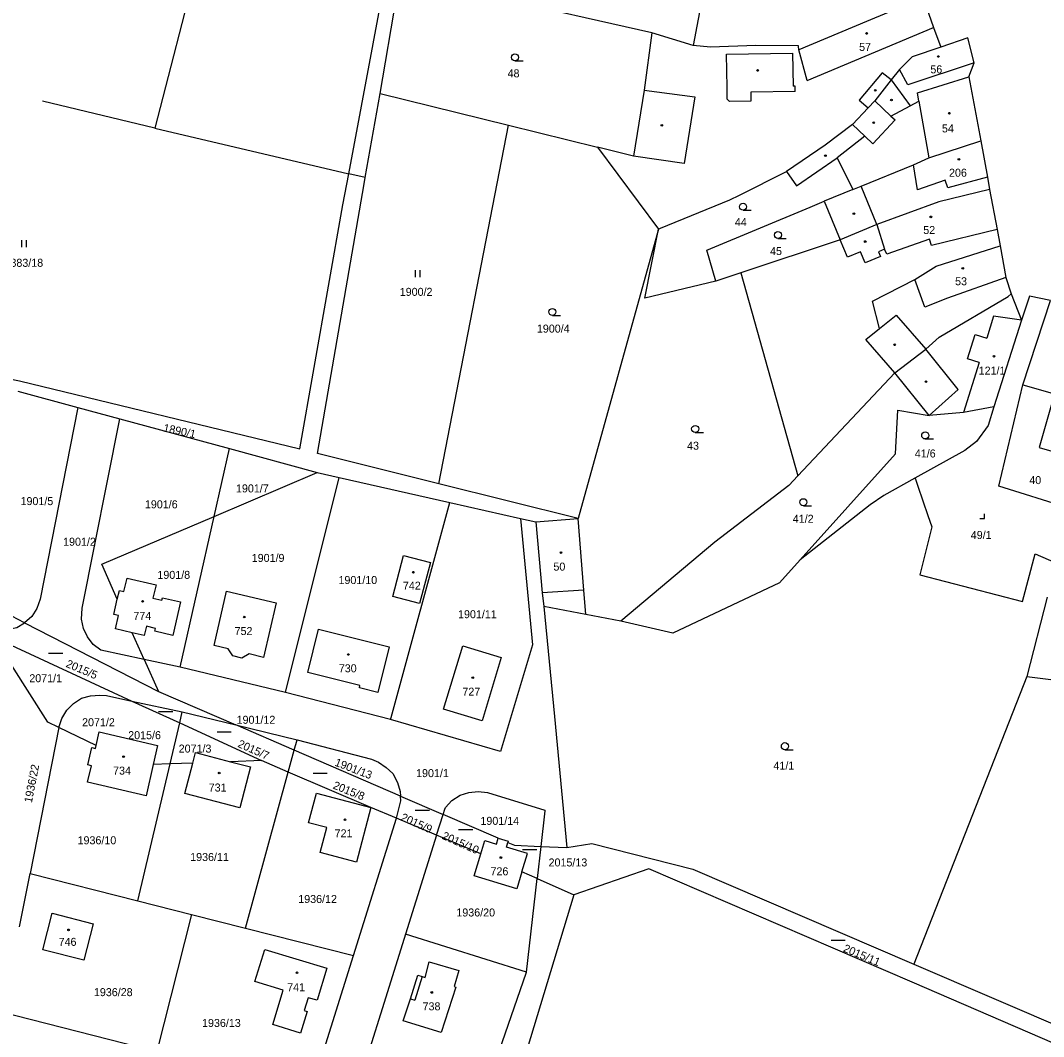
# Model space of a CAD drawing. Extents: x -793666 to -785424, y -1118958 to -1108761.
# Drawn here: x -788490.9 to -788273.7, y -1116664.5 to -1116448.6 of the extents above; entities that cross this region are included whole.
import ezdxf

# ---------------------------------------------------------------- set-up
doc = ezdxf.new("R2010")
doc.units = 0
for name, color, linetype in [('Hranice parcel', 7, 'Continuous'), ('Parcelní čísla', 7, 'Continuous'), ('Vnitřní kresba', 7, 'Continuous'), ('Značky budov', 7, 'Continuous'), ('Značky kultur', 7, 'Continuous')]:
    doc.layers.add(name, color=color, linetype=linetype)

msp = doc.modelspace()

# ---------------------------------------------------------------- linework, layer by layer
at = {"layer": 'Hranice parcel'}
for p, q in [((-788414.54, -1116464.14), (-788410.35, -1116439.11)), ((-788356.85, -1116451.26), (-788410.35, -1116439.11)), ((-788348.08, -1116453.93), (-788356.85, -1116451.26)), ((-788289.56, -1116460.58), (-788286.99, -1116474.21)), ((-788417.71, -1116481.98), (-788414.54, -1116464.14)), ((-788414.54, -1116464.14), (-788387.31, -1116470.88)), ((-788462.39, -1116471.52), (-788486.23, -1116465.77)), ((-788402.13, -1116547.05), (-788387.31, -1116470.88)), ((-788387.31, -1116470.88), (-788368.39, -1116475.54)), ((-788462.39, -1116471.52), (-788421.23, -1116481.16)), ((-788368.39, -1116475.54), (-788355.49, -1116492.94)), ((-788417.71, -1116481.98), (-788421.23, -1116481.16)), ((-788314.17, -1116484.54), (-788320.25, -1116487.03)), ((-788320.25, -1116487.03), (-788316.88, -1116495.2)), ((-788355.49, -1116492.94), (-788372.54, -1116554.44)), ((-788316.88, -1116495.2), (-788338.01, -1116502.23)), ((-788338.01, -1116502.23), (-788343.25, -1116503.97)), ((-788338.01, -1116502.23), (-788325.84, -1116545.35)), ((-788280.56, -1116506.71), (-788278.35, -1116512.25)), ((-788278.12, -1116526), (-788272.23, -1116508.1)), ((-788278.35, -1116512.25), (-788284.27, -1116530.68)), ((-788305.27, -1116523.5), (-788325.84, -1116545.35)), ((-788297.98, -1116532.55), (-788305.27, -1116523.5)), ((-788491.48, -1116527.33), (-788478.73, -1116530.8)), ((-788478.73, -1116530.8), (-788469.84, -1116533.23)), ((-788469.84, -1116533.23), (-788446.58, -1116539.57)), ((-788449.82, -1116553.98), (-788446.58, -1116539.57)), ((-788446.58, -1116539.57), (-788427.9, -1116544.66)), ((-788290.41, -1116539.96), (-788301, -1116545.84)), ((-788449.82, -1116553.98), (-788427.9, -1116544.66)), ((-788427.9, -1116544.66), (-788423.28, -1116545.71)), ((-788434.66, -1116591.36), (-788423.28, -1116545.71)), ((-788423.28, -1116545.71), (-788399.74, -1116551.03)), ((-788301, -1116545.84), (-788307.59, -1116549.5)), ((-788372.54, -1116554.44), (-788402.13, -1116547.05)), ((-788399.74, -1116551.03), (-788384.76, -1116554.42)), ((-788307.59, -1116549.5), (-788310.51, -1116551.48)), ((-788310.51, -1116551.48), (-788325.4, -1116563.23)), ((-788457.04, -1116586.01), (-788449.82, -1116553.98)), ((-788384.76, -1116554.42), (-788381.52, -1116555.15)), ((-788381.52, -1116555.15), (-788372.54, -1116554.44)), ((-788470.37, -1116571.57), (-788469.94, -1116569.69)), ((-788471.11, -1116574.8), (-788470.37, -1116571.57)), ((-788272.94, -1116571.1), (-788277.22, -1116587.97)), ((-788490.08, -1116576.56), (-788492.74, -1116575.19)), ((-788370.92, -1116574.81), (-788379.78, -1116573.09)), ((-788363.45, -1116576.26), (-788370.92, -1116574.81)), ((-788490.08, -1116576.56), (-788461.64, -1116591.17)), ((-788467.2, -1116578.68), (-788470.78, -1116577.86)), ((-788464.67, -1116584.38), (-788467.2, -1116578.68)), ((-788464.65, -1116579.27), (-788467.2, -1116578.68)), ((-788496.63, -1116579.65), (-788467.26, -1116593.19)), ((-788457.04, -1116586.01), (-788464.67, -1116584.38)), ((-788464.67, -1116584.38), (-788461.64, -1116591.17)), ((-788434.66, -1116591.36), (-788457.04, -1116586.01)), ((-788277.22, -1116587.97), (-788301.21, -1116649.08)), ((-788277.22, -1116587.97), (-788263.13, -1116589.78)), ((-788461.64, -1116591.17), (-788445.21, -1116598.27)), ((-788412.36, -1116597.13), (-788434.66, -1116591.36)), ((-788467.26, -1116593.19), (-788456.58, -1116595.52)), ((-788467.26, -1116593.19), (-788457.13, -1116597.86)), ((-788457.13, -1116597.86), (-788456.58, -1116595.52)), ((-788456.58, -1116595.52), (-788445.21, -1116598.27)), ((-788482.78, -1116598.82), (-788488.9, -1116629.83)), ((-788474.89, -1116602.67), (-788482.78, -1116598.82)), ((-788459.18, -1116606.54), (-788457.13, -1116597.86)), ((-788457.13, -1116597.86), (-788439.79, -1116605.86)), ((-788445.21, -1116598.27), (-788432.2, -1116601.41)), ((-788432.81, -1116603.63), (-788445.21, -1116598.27)), ((-788474.89, -1116602.67), (-788474.22, -1116599.75)), ((-788474.22, -1116599.75), (-788461.82, -1116602.62)), ((-788475.02, -1116603.25), (-788474.89, -1116602.67)), ((-788461.82, -1116602.62), (-788462.75, -1116606.67)), ((-788432.81, -1116603.63), (-788432.2, -1116601.41)), ((-788434.08, -1116608.29), (-788432.81, -1116603.63)), ((-788410.24, -1116613.38), (-788432.81, -1116603.63)), ((-788466.02, -1116635.65), (-788459.18, -1116606.54)), ((-788462.75, -1116606.67), (-788464.27, -1116613.33)), ((-788459.18, -1116606.54), (-788462.75, -1116606.67)), ((-788454.34, -1116606.37), (-788459.18, -1116606.54)), ((-788439.79, -1116605.86), (-788446.34, -1116606.09)), ((-788434.08, -1116608.29), (-788439.79, -1116605.86)), ((-788443.12, -1116641.46), (-788434.08, -1116608.29)), ((-788410.24, -1116613.38), (-788401.19, -1116617.29)), ((-788379.57, -1116616.52), (-788380.44, -1116624.08)), ((-788420.23, -1116647.28), (-788411.08, -1116618.07)), ((-788402.57, -1116621.69), (-788411.08, -1116618.07)), ((-788402.57, -1116621.69), (-788401.19, -1116617.29)), ((-788389.49, -1116622.34), (-788401.19, -1116617.29)), ((-788402.57, -1116621.69), (-788409.17, -1116642.74)), ((-788393.2, -1116625.68), (-788402.57, -1116621.69)), ((-788380.44, -1116624.08), (-788381.23, -1116630.92)), ((-788380.44, -1116624.08), (-788374.9, -1116624.32)), ((-788381.23, -1116630.92), (-788384.47, -1116629.47)), ((-788491.13, -1116641.15), (-788488.9, -1116629.83)), ((-788488.9, -1116629.83), (-788466.02, -1116635.65)), ((-788383.5, -1116650.8), (-788381.23, -1116630.92)), ((-788381.23, -1116630.92), (-788373.45, -1116634.4)), ((-788466.02, -1116635.65), (-788454.6, -1116638.55)), ((-788373.45, -1116634.4), (-788420.97, -1116791.2)), ((-788454.6, -1116638.55), (-788461.96, -1116667.65)), ((-788454.6, -1116638.55), (-788443.12, -1116641.46)), ((-788443.12, -1116641.46), (-788420.23, -1116647.28)), ((-788409.17, -1116642.74), (-788413.34, -1116656.08)), ((-788383.5, -1116650.8), (-788409.17, -1116642.74)), ((-788429.2, -1116676), (-788420.23, -1116647.28)), ((-788394.62, -1116682.97), (-788383.5, -1116650.8)), ((-788413.34, -1116656.08), (-788419.35, -1116675.22)), ((-788495.6, -1116659.1), (-788461.96, -1116667.65))]:
    msp.add_line(p, q, dxfattribs=at)
for points in [[(-788421.23, -1116481.16), (-788413.32, -1116439.14), (-788406.38, -1116409.89), (-788400.46, -1116386.05)], [(-788436.34, -1116390.99), (-788453.24, -1116436.02), (-788462.39, -1116471.52)], [(-788340.92, -1116418.9), (-788346.24, -1116444.12), (-788348.08, -1116453.93)], [(-788299.17, -1116443.74), (-788311.32, -1116448.82), (-788325.63, -1116454.87), (-788325.73, -1116454.15), (-788325.75, -1116453.97), (-788334.82, -1116453.91), (-788344.45, -1116454.29), (-788348.08, -1116453.93)], [(-788299.17, -1116443.74), (-788299.11, -1116444.14), (-788297.03, -1116450.12), (-788295.49, -1116454.27)], [(-788356.85, -1116451.26), (-788358.47, -1116463.4), (-788360.8, -1116477.42), (-788368.39, -1116475.54)], [(-788289.56, -1116460.58), (-788288.46, -1116457.62), (-788289.74, -1116452.32), (-788295.49, -1116454.27)], [(-788295.49, -1116454.27), (-788301.61, -1116456.36), (-788304.29, -1116458.99), (-788306.05, -1116461.23), (-788309.55, -1116465.7)], [(-788309.55, -1116465.7), (-788306.09, -1116468.91), (-788302.01, -1116466.71), (-788300.17, -1116465.72), (-788300.48, -1116463.95), (-788289.56, -1116460.58)], [(-788309.55, -1116465.7), (-788310.93, -1116467.17), (-788314.26, -1116470.73), (-788320.07, -1116475.09), (-788328.29, -1116480.68)], [(-788314.17, -1116484.54), (-788312.43, -1116483.83), (-788301.3, -1116479.26), (-788298.04, -1116477.8), (-788286.99, -1116474.21)], [(-788286.99, -1116474.21), (-788285.6, -1116481.93), (-788285.15, -1116484.49)], [(-788328.29, -1116480.68), (-788326.18, -1116483.71), (-788317.55, -1116477.81), (-788314.17, -1116484.54)], [(-788614.4, -1116497.78), (-788554.99, -1116511.96), (-788491.11, -1116525.14), (-788431.6, -1116539.59), (-788422.48, -1116487.78), (-788421.23, -1116481.16)], [(-788355.49, -1116492.94), (-788355, -1116492.75), (-788340.3, -1116486.72), (-788338.27, -1116485.7), (-788328.29, -1116480.68)], [(-788402.13, -1116547.05), (-788427.84, -1116540.63), (-788417.94, -1116483.29), (-788417.71, -1116481.98)], [(-788285.15, -1116484.49), (-788295.96, -1116487.15), (-788309.07, -1116491.92), (-788316.88, -1116495.2)], [(-788285.15, -1116484.49), (-788283.53, -1116492.98), (-788282.91, -1116496.51)], [(-788343.25, -1116503.97), (-788345.2, -1116497.43), (-788323.28, -1116488.3), (-788320.25, -1116487.03)], [(-788343.25, -1116503.97), (-788358.35, -1116507.58), (-788355.49, -1116492.94)], [(-788305.27, -1116523.5), (-788311.46, -1116516.37), (-788308.5, -1116514.03), (-788310.02, -1116508.25), (-788301.03, -1116503.62), (-788296.47, -1116500.79), (-788282.91, -1116496.51)], [(-788282.91, -1116496.51), (-788281.71, -1116503.19), (-788280.56, -1116506.71)], [(-788305.27, -1116523.5), (-788298.71, -1116518.45), (-788295.85, -1116515.9), (-788281.22, -1116507.22), (-788280.56, -1116506.71)], [(-788272.23, -1116508.1), (-788276.71, -1116507.17), (-788278.35, -1116512.25)], [(-788268.24, -1116552.2), (-788283.18, -1116547.55), (-788278.12, -1116526)], [(-788278.12, -1116526), (-788271.36, -1116527.92), (-788274.6, -1116539.35), (-788268.5, -1116541.08)], [(-788478.73, -1116530.8), (-788486.77, -1116571.58), (-788487.43, -1116573.53), (-788488.51, -1116575.22), (-788490.08, -1116576.56)], [(-788325.4, -1116563.23), (-788305.13, -1116540.66), (-788304.64, -1116531.4), (-788297.98, -1116532.55)], [(-788284.27, -1116530.68), (-788290.69, -1116531.87), (-788297.98, -1116532.55)], [(-788284.27, -1116530.68), (-788285.48, -1116534.65), (-788287.95, -1116538.05), (-788290.41, -1116539.96)], [(-788464.67, -1116584.38), (-788473.88, -1116582.41), (-788475.48, -1116581.2), (-788476.71, -1116579.54), (-788477.56, -1116577.77), (-788477.94, -1116575.8), (-788477.84, -1116573.5), (-788469.84, -1116533.23)], [(-788325.84, -1116545.35), (-788327.76, -1116547.39), (-788343.5, -1116559.45), (-788363.45, -1116576.26)], [(-788301, -1116545.84), (-788300.92, -1116546.07), (-788300.42, -1116547.52), (-788298.26, -1116553.75), (-788297.42, -1116556.2), (-788299.98, -1116566.4), (-788278.14, -1116572.05), (-788275.49, -1116561.89), (-788271.12, -1116563.8)], [(-788412.36, -1116597.13), (-788412.24, -1116596.7), (-788399.74, -1116551.03)], [(-788470.37, -1116571.57), (-788473.68, -1116564.13), (-788449.82, -1116553.98)], [(-788384.76, -1116554.42), (-788382.22, -1116581.27), (-788388.99, -1116603.9), (-788412.36, -1116597.13)], [(-788381.52, -1116555.15), (-788380.15, -1116570.22), (-788379.78, -1116573.09)], [(-788370.92, -1116574.81), (-788371.33, -1116569.66), (-788372.54, -1116554.44)], [(-788411.9, -1116570.96), (-788409.6, -1116562.26), (-788403.89, -1116563.78), (-788406.2, -1116572.49), (-788411.9, -1116570.96)], [(-788325.4, -1116563.23), (-788329.74, -1116568.06), (-788352.38, -1116578.79), (-788363.45, -1116576.26)], [(-788469.94, -1116569.69), (-788468.96, -1116569.91), (-788468.3, -1116567.07), (-788462.15, -1116568.49), (-788462.81, -1116571.32), (-788460.92, -1116571.76), (-788460.8, -1116571.24), (-788456.93, -1116572.13), (-788458.57, -1116579.24), (-788462.43, -1116578.35), (-788462.29, -1116577.76), (-788464.19, -1116577.32), (-788464.65, -1116579.27)], [(-788442.4, -1116583.2), (-788443.94, -1116584.07), (-788445.82, -1116583.61), (-788446.81, -1116582.13), (-788449.81, -1116581.39), (-788447.19, -1116569.82), (-788436.65, -1116572.36), (-788439.34, -1116583.96), (-788442.4, -1116583.2)], [(-788470.78, -1116577.86), (-788470.15, -1116575.03), (-788471.11, -1116574.8)], [(-788379.78, -1116573.09), (-788377.55, -1116596.5), (-788374.9, -1116624.32)], [(-788500.6, -1116576.98), (-788496.27, -1116577.93), (-788493.73, -1116577.98), (-788491.73, -1116577.56), (-788490.08, -1116576.56)], [(-788412.63, -1116581.69), (-788415.05, -1116591.37), (-788418.98, -1116590.42), (-788418.85, -1116589.91), (-788429.95, -1116587.14), (-788427.64, -1116577.93), (-788412.63, -1116581.69)], [(-788482.78, -1116598.82), (-788485.13, -1116597.68), (-788496.63, -1116579.65)], [(-788392.93, -1116597.38), (-788401.09, -1116594.91), (-788397.03, -1116581.5), (-788388.88, -1116583.96), (-788392.93, -1116597.38)], [(-788482.78, -1116598.82), (-788482.17, -1116596.88), (-788481.1, -1116595.16), (-788479.69, -1116593.75), (-788477.96, -1116592.61), (-788476.08, -1116592.08), (-788474.08, -1116591.93), (-788472.68, -1116592.01), (-788467.26, -1116593.19)], [(-788464.27, -1116613.33), (-788476.69, -1116610.46), (-788475.86, -1116606.94), (-788476.61, -1116606.76), (-788475.75, -1116603.08), (-788475.02, -1116603.25)], [(-788432.2, -1116601.41), (-788416.41, -1116605.58), (-788414.93, -1116606.22), (-788413.25, -1116607.31), (-788411.87, -1116608.62), (-788410.86, -1116610.49), (-788410.29, -1116612.42), (-788410.24, -1116613.38)], [(-788454.34, -1116606.37), (-788453.76, -1116604.15), (-788446.34, -1116606.09)], [(-788446.34, -1116606.09), (-788442.11, -1116607.2), (-788444.37, -1116615.89), (-788456.02, -1116612.86), (-788454.34, -1116606.37)], [(-788411.08, -1116618.07), (-788416.52, -1116615.83), (-788434.08, -1116608.29)], [(-788416.52, -1116615.83), (-788419.57, -1116627.43), (-788427.33, -1116625.36), (-788425.9, -1116620.07), (-788429.78, -1116619.05), (-788428.11, -1116612.77), (-788416.52, -1116615.83)], [(-788411.08, -1116618.07), (-788410.18, -1116614.42), (-788410.24, -1116613.38)], [(-788401.19, -1116617.29), (-788400.85, -1116616.17), (-788400.72, -1116615.8), (-788399.33, -1116614.36), (-788397.6, -1116613.21), (-788395.73, -1116612.63), (-788393.73, -1116612.44), (-788391.75, -1116612.66), (-788379.57, -1116616.41), (-788379.57, -1116616.52)], [(-788393.2, -1116625.68), (-788392.34, -1116622.83), (-788389.84, -1116623.61), (-788389.49, -1116622.34)], [(-788389.49, -1116622.34), (-788387.39, -1116623), (-788387.45, -1116623.22)], [(-788384.47, -1116629.47), (-788383.3, -1116625.61), (-788387.74, -1116624.25), (-788387.45, -1116623.22)], [(-788387.45, -1116623.22), (-788386.05, -1116623.83), (-788380.44, -1116624.08)], [(-788374.9, -1116624.32), (-788369.6, -1116623.49), (-788348.19, -1116628.91), (-788301.21, -1116649.08)], [(-788384.47, -1116629.47), (-788385.57, -1116633.1), (-788394.62, -1116630.31), (-788393.2, -1116625.68)], [(-788266.33, -1116668.19), (-788268.66, -1116667.18), (-788301.6, -1116652.96), (-788357.49, -1116628.83), (-788373.45, -1116634.4)], [(-788477.45, -1116648.28), (-788486.16, -1116646.06), (-788484.21, -1116638.29), (-788475.47, -1116640.51), (-788477.45, -1116648.28)], [(-788439.05, -1116645.98), (-788425.86, -1116649.96), (-788427.95, -1116656.78), (-788429.87, -1116656.22), (-788430.71, -1116658.95), (-788430.04, -1116659.16), (-788431.46, -1116663.74), (-788437.38, -1116661.92), (-788435.12, -1116654.61), (-788441.14, -1116652.76), (-788439.05, -1116645.98)], [(-788405.03, -1116651.91), (-788404.17, -1116648.6), (-788397.87, -1116650.44), (-788398.88, -1116653.84), (-788398.5, -1116653.96), (-788401.58, -1116663.64), (-788409.65, -1116661.12), (-788408.1, -1116656.46), (-788406.56, -1116651.42), (-788405.62, -1116651.72), (-788405.03, -1116651.91)], [(-788301.21, -1116649.08), (-788267.3, -1116663.67), (-788264.77, -1116664.43)]]:
    msp.add_lwpolyline(points, dxfattribs=at)
at = {"layer": 'Vnitřní kresba'}
for p, q in [((-788323.88, -1116461.34), (-788297.03, -1116450.12)), ((-788341.03, -1116455.79), (-788327, -1116455.55)), ((-788327, -1116455.55), (-788326.88, -1116462.58)), ((-788323.88, -1116461.34), (-788325.63, -1116454.87)), ((-788340.91, -1116462.83), (-788341.03, -1116455.79)), ((-788288.46, -1116457.62), (-788302.54, -1116462.25)), ((-788307.97, -1116459.7), (-788312.83, -1116465.57)), ((-788306.05, -1116461.23), (-788307.97, -1116459.7)), ((-788302.54, -1116462.25), (-788304.29, -1116458.99)), ((-788306.05, -1116461.23), (-788302.01, -1116466.71)), ((-788358.47, -1116463.4), (-788347.76, -1116464.85)), ((-788340.89, -1116465.33), (-788340.91, -1116462.83)), ((-788326.44, -1116463.68), (-788335.84, -1116463.84)), ((-788335.84, -1116463.84), (-788335.83, -1116465.75)), ((-788326.42, -1116462.55), (-788326.88, -1116462.58)), ((-788326.44, -1116463.68), (-788326.42, -1116462.55)), ((-788347.76, -1116464.85), (-788350.04, -1116478.99)), ((-788340.38, -1116465.8), (-788340.89, -1116465.33)), ((-788335.83, -1116465.75), (-788340.38, -1116465.8)), ((-788312.83, -1116465.57), (-788310.93, -1116467.17)), ((-788300.17, -1116465.72), (-788298.04, -1116477.8)), ((-788311.62, -1116473.22), (-788314.26, -1116470.73)), ((-788305.21, -1116469.72), (-788309.93, -1116474.82)), ((-788306.09, -1116468.91), (-788305.21, -1116469.72)), ((-788311.62, -1116473.22), (-788317.55, -1116477.81)), ((-788309.93, -1116474.82), (-788311.62, -1116473.22)), ((-788350.04, -1116478.99), (-788360.8, -1116477.42)), ((-788300.44, -1116484.57), (-788301.3, -1116479.26)), ((-788309.07, -1116491.92), (-788312.43, -1116483.83)), ((-788294.56, -1116482.56), (-788300.44, -1116484.57)), ((-788294.02, -1116484.13), (-788294.56, -1116482.56)), ((-788285.6, -1116481.93), (-788294.02, -1116484.13)), ((-788309.07, -1116491.92), (-788307.44, -1116497.18)), ((-788283.53, -1116492.98), (-788297.46, -1116496.43)), ((-788315.34, -1116498.92), (-788316.88, -1116495.2)), ((-788297.93, -1116495.09), (-788306.98, -1116498.25)), ((-788297.46, -1116496.43), (-788297.93, -1116495.09)), ((-788312.57, -1116497.73), (-788315.34, -1116498.92)), ((-788311.54, -1116500.12), (-788312.57, -1116497.73)), ((-788308.31, -1116498.73), (-788311.54, -1116500.12)), ((-788307.44, -1116497.18), (-788308.74, -1116497.74)), ((-788308.74, -1116497.74), (-788308.31, -1116498.73)), ((-788306.98, -1116498.25), (-788307.44, -1116497.18)), ((-788281.71, -1116503.19), (-788294.09, -1116507.59)), ((-788298.94, -1116509.5), (-788301.03, -1116503.62)), ((-788294.09, -1116507.59), (-788298.94, -1116509.5)), ((-788308.5, -1116514.03), (-788304.98, -1116511.24)), ((-788304.98, -1116511.24), (-788298.71, -1116518.45)), ((-788284.29, -1116511.44), (-788285.75, -1116516.09)), ((-788278.35, -1116512.25), (-788284.29, -1116511.44)), ((-788289.83, -1116520.46), (-788288.25, -1116515.35)), ((-788288.25, -1116515.35), (-788285.75, -1116516.09)), ((-788291.8, -1116527.01), (-788298.71, -1116518.45)), ((-788287.38, -1116521.26), (-788289.83, -1116520.46)), ((-788287.38, -1116521.26), (-788290.69, -1116531.87)), ((-788297.98, -1116532.55), (-788291.8, -1116527.01)), ((-788371.33, -1116569.66), (-788380.15, -1116570.22)), ((-788405.62, -1116651.72), (-788407.19, -1116656.78)), ((-788408.1, -1116656.46), (-788407.19, -1116656.78))]:
    msp.add_line(p, q, dxfattribs=at)
at = {"layer": 'Značky budov'}
for centre in [(-788311.27, -1116451.36), (-788296.03, -1116456.26), (-788334.41, -1116459.23), (-788309.42, -1116463.43), (-788305.99, -1116465.51), (-788293.69, -1116468.31), (-788354.75, -1116470.9), (-788309.76, -1116470.32), (-788320, -1116477.34), (-788291.67, -1116478.1), (-788313.97, -1116489.64), (-788297.62, -1116490.33), (-788311.56, -1116495.58), (-788290.85, -1116501.27), (-788305.3, -1116517.51), (-788284.23, -1116519.94), (-788298.66, -1116525.34), (-788376.15, -1116561.65), (-788407.51, -1116565.82), (-788465, -1116572.03), (-788443.4, -1116575.35), (-788421.31, -1116583.31), (-788394.89, -1116588.24), (-788469.05, -1116605.01), (-788448.74, -1116608.5), (-788422.01, -1116618.43), (-788388.93, -1116626.45), (-788480.72, -1116641.82), (-788432.2, -1116650.93), (-788403.59, -1116655.11)]:
    msp.add_circle(centre, 0.175, dxfattribs=at)
at = {"layer": 'Značky kultur'}
for p, q in [((-788385.94, -1116457.19), (-788384.19, -1116457.19)), ((-788337.5, -1116488.93), (-788335.75, -1116488.93)), ((-788490.68, -1116496.79), (-788490.68, -1116495.29)), ((-788489.68, -1116496.79), (-788489.68, -1116495.29)), ((-788330.1, -1116494.93), (-788328.35, -1116494.93)), ((-788407.06, -1116503.13), (-788407.06, -1116501.63)), ((-788406.06, -1116503.13), (-788406.06, -1116501.63)), ((-788377.99, -1116511.28), (-788376.24, -1116511.28)), ((-788347.67, -1116536.14), (-788345.92, -1116536.14)), ((-788298.82, -1116537.52), (-788297.07, -1116537.52)), ((-788324.7, -1116551.71), (-788322.95, -1116551.71)), ((-788286.23, -1116554.42), (-788286.23, -1116553.42)), ((-788287.23, -1116554.42), (-788286.23, -1116554.42)), ((-788484.97, -1116583), (-788481.97, -1116583)), ((-788461.61, -1116595.4), (-788458.61, -1116595.4)), ((-788449.18, -1116599.76), (-788446.18, -1116599.76)), ((-788328.62, -1116603.54), (-788326.87, -1116603.54)), ((-788428.79, -1116608.55), (-788425.79, -1116608.55)), ((-788407.1, -1116616.4), (-788404.1, -1116616.4)), ((-788397.9, -1116620.47), (-788394.9, -1116620.47)), ((-788384.3, -1116624.72), (-788381.3, -1116624.72)), ((-788318.8, -1116644.03), (-788315.8, -1116644.03))]:
    msp.add_line(p, q, dxfattribs=at)
for centre in [(-788385.94, -1116456.44), (-788337.5, -1116488.18), (-788330.1, -1116494.18), (-788377.99, -1116510.53), (-788347.67, -1116535.39), (-788298.82, -1116536.77), (-788324.7, -1116550.96), (-788328.62, -1116602.79)]:
    msp.add_circle(centre, 0.75, dxfattribs=at)

# ---------------------------------------------------------------- texts
at = {"layer": 'Parcelní čísla'}
for s, p in [('57', (-788312.86, -1116455.08)), ('48', (-788387.5, -1116460.69)), ('56', (-788297.73, -1116459.84)), ('54', (-788295.27, -1116472.39)), ('206', (-788293.77, -1116481.8)), ('44', (-788339.24, -1116492.28)), ('52', (-788299.24, -1116493.97)), ('45', (-788331.77, -1116498.44)), ('1883/18', (-788494.33, -1116500.94)), ('53', (-788292.48, -1116504.86)), ('1900/2', (-788410.4, -1116507.11)), ('1900/4', (-788381.28, -1116514.92)), ('121/1', (-788287.48, -1116523.85)), ('43', (-788349.39, -1116539.8)), ('41/6', (-788301.03, -1116541.45)), ('40', (-788276.72, -1116547.11)), ('1901/7', (-788445.17, -1116548.87)), ('1901/5', (-788490.92, -1116551.57)), ('1901/6', (-788464.51, -1116552.25)), ('41/2', (-788326.95, -1116555.32)), ('49/1', (-788289.15, -1116558.77)), ('1901/2', (-788481.88, -1116560.2)), ('1901/9', (-788441.83, -1116563.64)), ('50', (-788377.77, -1116565.49)), ('1901/8', (-788461.86, -1116567.24)), ('1901/10', (-788423.41, -1116568.34)), ('742', (-788409.73, -1116569.53)), ('774', (-788466.96, -1116575.95)), ('1901/11', (-788398.02, -1116575.6)), ('752', (-788445.47, -1116579.18)), ('730', (-788423.34, -1116587.09)), ('2071/1', (-788489.06, -1116589.2)), ('727', (-788397.1, -1116592.06)), ('2071/2', (-788477.85, -1116598.55)), ('1901/12', (-788445.04, -1116598.03)), ('2015/6', (-788468.06, -1116601.3)), ('2071/3', (-788457.34, -1116604.15)), ('734', (-788471.27, -1116608.83)), ('1901/1', (-788406.93, -1116609.36)), ('41/1', (-788331.05, -1116607.77)), ('731', (-788450.96, -1116612.42)), ('1901/14', (-788393.27, -1116619.5)), ('721', (-788424.23, -1116622.15)), ('1936/10', (-788478.81, -1116623.63)), ('1936/11', (-788454.9, -1116627.19)), ('2015/13', (-788378.8, -1116628.34)), ('726', (-788391.13, -1116630.22)), ('1936/12', (-788431.95, -1116636.11)), ('1936/20', (-788398.38, -1116638.97)), ('746', (-788482.83, -1116645.21)), ('741', (-788434.3, -1116654.85)), ('1936/28', (-788475.34, -1116655.9)), ('738', (-788405.55, -1116658.91)), ('1936/13', (-788452.38, -1116662.44))]:
    msp.add_text(s, height=1.7, dxfattribs=at).set_placement(p)
for s, rotation, p in [('1890/1', 348, (-788460.71, -1116535.92)), ('2015/5', 337, (-788481.43, -1116585.89)), ('2015/7', 336, (-788444.95, -1116602.89)), ('1901/13', 339, (-788424.35, -1116606.88)), ('1936/22', 79, (-788488.52, -1116614.91)), ('2015/8', 338, (-788424.72, -1116611.74)), ('2015/9', 336, (-788410.33, -1116618.49)), ('2015/10', 336, (-788401.57, -1116622.42)), ('2015/11', 337, (-788316.38, -1116646.36))]:
    msp.add_text(s, height=1.7, rotation=rotation, dxfattribs=at).set_placement(p)

doc.saveas('drawing.dxf')
